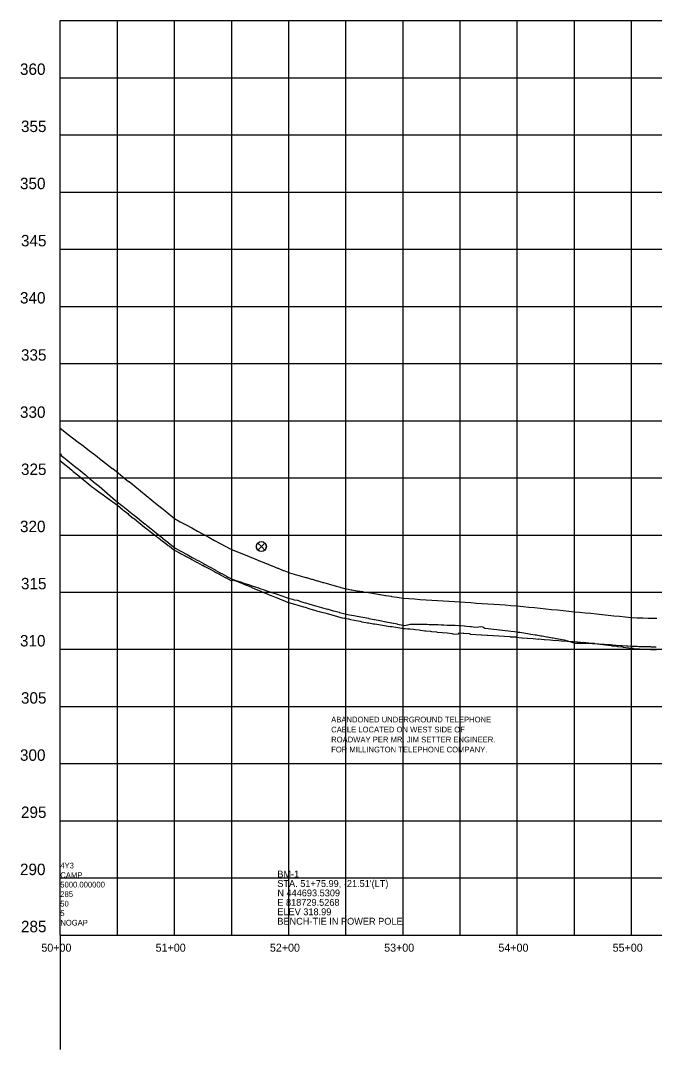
# Model space of a CAD drawing. Extents: x 816928 to 825690, y 436959 to 448212.
# Drawn here: x 817253 to 817808, y 446338 to 447238 of the extents above; entities that cross this region are included whole.
import ezdxf

# ---------------------------------------------------------------- set-up
doc = ezdxf.new("R2010")
doc.units = 0
for name, color, linetype in [('DESIGN - SHEET - Corner Text', 7, 'Continuous'), ('DESIGN - SHEET - Light Grid', 7, 'Continuous'), ('SURVEY - PROFILE - Control with Text', 7, 'Continuous'), ('SURVEY - PROFILE - Ground Line with Text', 7, 'Continuous'), ('SURVEY - PROFILE - Utilities - Gas with Text', 7, 'Continuous'), ('SURVEY - PROFILE - Utilities - Telephone with Text', 7, 'Continuous'), ('SURVEY - PROFILE - Utilities - Water with Text', 7, 'Continuous')]:
    doc.layers.add(name, color=color, linetype=linetype)

msp = doc.modelspace()

# ---------------------------------------------------------------- linework, layer by layer
at = {"layer": 'DESIGN - SHEET - Light Grid'}
for p, q in [((817287.73, 446437.63), (817287.73, 447237.63)), ((817287.73, 446437.63), (817287.73, 447237.63)), ((817287.73, 447237.63), (818716.11, 447237.63)), ((817287.73, 447237.63), (818716.11, 447237.63)), ((817337.73, 446437.63), (817337.73, 447237.63)), ((817387.73, 446437.63), (817387.73, 447237.63)), ((817437.73, 446437.63), (817437.73, 447237.63)), ((817487.73, 446437.63), (817487.73, 447237.63)), ((817537.73, 446437.63), (817537.73, 447237.63)), ((817587.73, 446437.63), (817587.73, 447237.63)), ((817637.73, 446437.63), (817637.73, 447237.63)), ((817687.73, 446437.63), (817687.73, 447237.63)), ((817737.73, 446437.63), (817737.73, 447237.63)), ((817787.73, 446437.63), (817787.73, 447237.63)), ((817287.73, 447187.63), (818716.11, 447187.63)), ((817287.73, 447137.63), (818716.11, 447137.63)), ((817287.73, 447087.63), (818716.11, 447087.63)), ((817287.73, 447037.63), (818716.11, 447037.63)), ((817287.73, 446987.63), (818716.11, 446987.63)), ((817287.73, 446937.63), (818716.11, 446937.63)), ((817287.73, 446887.63), (818716.11, 446887.63)), ((817287.73, 446837.63), (818716.11, 446837.63)), ((817287.73, 446787.63), (818716.11, 446787.63)), ((817287.73, 446737.63), (818716.11, 446737.63)), ((817287.73, 446687.63), (818716.11, 446687.63)), ((817287.73, 446637.63), (818716.11, 446637.63)), ((817287.73, 446587.63), (818716.11, 446587.63)), ((817287.73, 446537.63), (818716.11, 446537.63)), ((817287.73, 446487.63), (818716.11, 446487.63)), ((817287.73, 446437.63), (818716.11, 446437.63)), ((817287.73, 446437.63), (817287.73, 446337.63)), ((817287.73, 446437.63), (818716.11, 446437.63))]:
    msp.add_line(p, q, dxfattribs=at)
at = {"layer": 'SURVEY - PROFILE - Control with Text'}
for p, q in [((817460.64, 446780.58), (817463.72, 446777.5)), ((817463.72, 446777.5), (817466.81, 446780.59)), ((817460.66, 446774.44), (817463.72, 446777.5)), ((817463.72, 446777.5), (817466.8, 446774.43))]:
    msp.add_line(p, q, dxfattribs=at)
for points in [[(817460.66, 446780.57), (817463.72, 446777.5), (817460.67, 446774.45), (817460.42, 446774.7), (817460.16, 446775.03), (817460, 446775.27), (817459.83, 446775.59), (817459.68, 446775.92), (817459.59, 446776.2), (817459.51, 446776.46), (817459.45, 446776.75), (817459.41, 446777.04), (817459.39, 446777.3), (817459.38, 446777.63), (817459.4, 446777.9), (817459.43, 446778.14), (817459.46, 446778.34), (817459.51, 446778.57), (817459.59, 446778.85), (817459.66, 446779.05), (817459.76, 446779.28), (817459.93, 446779.63), (817460.13, 446779.96), (817460.41, 446780.33)], [(817466.8, 446780.57), (817463.72, 446777.5), (817466.79, 446774.43), (817466.98, 446774.63), (817467.21, 446774.91), (817467.44, 446775.24), (817467.58, 446775.49), (817467.77, 446775.9), (817467.87, 446776.18), (817467.95, 446776.47), (817468, 446776.71), (817468.05, 446777.03), (817468.07, 446777.28), (817468.08, 446777.59), (817468.06, 446777.9), (817468.04, 446778.11), (817467.99, 446778.39), (817467.95, 446778.58), (817467.87, 446778.84), (817467.74, 446779.2), (817467.65, 446779.4), (817467.54, 446779.62), (817467.32, 446779.96), (817467.07, 446780.3)]]:
    msp.add_lwpolyline(points, close=True, dxfattribs=at)
msp.add_circle((817463.73, 446777.51), 4.35, dxfattribs=at)
at = {"layer": 'SURVEY - PROFILE - Ground Line with Text'}
msp.add_lwpolyline([(817287.73, 446881.08), (817288.65, 446880.17), (817293.57, 446876.43), (817298.49, 446872.69), (817303.4, 446868.95), (817308.32, 446865.21), (817308.67, 446864.94), (817313.36, 446861.31), (817318.42, 446857.4), (817323.47, 446853.5), (817328.52, 446849.59), (817333.23, 446845.95), (817333.58, 446845.67), (817338.24, 446842.07), (817342.5, 446838.62), (817342.89, 446838.31), (817347.52, 446834.57), (817347.87, 446834.29), (817352.53, 446830.52), (817352.85, 446830.27), (817357.83, 446826.24), (817362.81, 446822.22), (817367.78, 446818.19), (817372.76, 446814.16), (817377.74, 446810.13), (817382.72, 446806.1), (817387.73, 446802.06), (817392.78, 446799.29), (817397.77, 446796.55), (817402.76, 446793.82), (817407.75, 446791.09), (817412.74, 446788.35), (817417.73, 446785.62), (817422.72, 446782.88), (817427.71, 446780.15), (817432.65, 446777.44), (817436.29, 446775.66), (817437.77, 446774.85), (817438.97, 446774.44), (817442.93, 446772.84), (817447.96, 446770.82), (817452.98, 446768.79), (817458, 446766.76), (817462.71, 446764.86), (817463.02, 446764.73), (817467.82, 446762.79), (817468.2, 446762.63), (817472.81, 446760.77), (817473.25, 446760.58), (817477.8, 446758.75), (817478.3, 446758.53), (817482.78, 446756.72), (817483.34, 446756.48), (817487.77, 446754.69), (817488.25, 446754.56), (817492.56, 446753.33), (817493.18, 446753.16), (817497.56, 446751.91), (817498.18, 446751.74), (817502.56, 446750.49), (817503.18, 446750.31), (817507.55, 446749.07), (817508.18, 446748.89), (817512.55, 446747.64), (817513.18, 446747.47), (817517.55, 446746.22), (817518.17, 446746.05), (817522.55, 446744.8), (817523.17, 446744.63), (817527.54, 446743.38), (817528.17, 446743.21), (817532.54, 446741.96), (817533.17, 446741.79), (817537.61, 446740.53), (817538.24, 446740.42), (817542.37, 446739.74), (817542.96, 446739.64), (817547.37, 446738.92), (817547.92, 446738.82), (817552.38, 446738.09), (817552.89, 446738.01), (817557.38, 446737.27), (817557.86, 446737.19), (817562.39, 446736.45), (817562.83, 446736.37), (817567.4, 446735.63), (817567.79, 446735.56), (817572.4, 446734.81), (817572.76, 446734.74), (817577.41, 446733.99), (817577.73, 446733.93), (817582.69, 446733.12), (817587.83, 446732.32), (817592.83, 446731.99), (817597.82, 446731.66), (817602.82, 446731.33), (817607.81, 446731.01), (817612.81, 446730.68), (817617.8, 446730.36), (817622.8, 446730.03), (817627.79, 446729.71), (817632.79, 446729.38), (817637.76, 446729.06), (817642.06, 446728.77), (817647.05, 446728.44), (817652.05, 446728.1), (817657.04, 446727.77), (817662.04, 446727.43), (817667.03, 446727.09), (817672.03, 446726.76), (817677.02, 446726.42), (817682.02, 446726.08), (817686.89, 446725.75), (817687.73, 446725.67), (817692.74, 446725.15), (817697.74, 446724.64), (817702.74, 446724.13), (817707.75, 446723.62), (817712.75, 446723.11), (817717.75, 446722.59), (817722.76, 446722.08), (817727.76, 446721.57), (817732.77, 446721.06), (817737.73, 446720.55), (817742.15, 446720.11), (817747.12, 446719.61), (817752.09, 446719.11), (817757.07, 446718.6), (817759.45, 446718.36), (817762.07, 446718.09), (817767.11, 446717.55), (817772.15, 446717.02), (817777.19, 446716.5), (817782.23, 446715.97), (817787.44, 446715.45), (817792.49, 446715.29), (817797.21, 446715.14), (817797.54, 446715.13), (817802.21, 446714.98), (817802.6, 446714.97), (817804.98, 446714.89), (817807.65, 446714.81), (817809.83, 446714.74)], dxfattribs=at)
at = {"layer": 'SURVEY - PROFILE - Utilities - Gas with Text'}
msp.add_lwpolyline([(817287.83, 446859.06), (817288.39, 446857.74), (817288.6, 446857.24), (817288.63, 446857.21), (817290.74, 446855.57), (817293.63, 446853.19), (817295.53, 446851.71), (817298.64, 446849.15), (817300.29, 446847.85), (817303.64, 446845.09), (817305.04, 446843.99), (817308.65, 446841), (817309.76, 446840.13), (817313.65, 446836.88), (817314.45, 446836.26), (817318.66, 446832.73), (817319.1, 446832.39), (817323.68, 446828.53), (817323.7, 446828.51), (817323.99, 446828.27), (817328.64, 446824.26), (817328.97, 446823.96), (817333.6, 446819.96), (817334.12, 446819.48), (817337.38, 446816.65), (817341.62, 446813.3), (817342.36, 446812.75), (817346.75, 446809.28), (817347.34, 446808.83), (817351.87, 446805.25), (817352.32, 446804.91), (817356.99, 446801.2), (817357.3, 446800.97), (817362.12, 446797.14), (817362.28, 446797.02), (817363.23, 446796.26), (817367.2, 446793.07), (817367.26, 446793.02), (817370.15, 446790.69), (817372.19, 446789.06), (817372.25, 446789.01), (817377.07, 446785.16), (817377.27, 446785), (817381.94, 446781.27), (817382.28, 446781), (817386.82, 446777.38), (817387.29, 446777.01), (817388.32, 446776.19), (817388.77, 446775.94), (817393.25, 446773.49), (817393.8, 446773.19), (817398.24, 446770.76), (817398.82, 446770.44), (817403.22, 446768.03), (817403.85, 446767.69), (817408.21, 446765.3), (817408.87, 446764.93), (817413.2, 446762.57), (817413.9, 446762.18), (817418.19, 446759.84), (817418.92, 446759.43), (817423.17, 446757.1), (817423.95, 446756.67), (817428.16, 446754.37), (817428.97, 446753.92), (817433.15, 446751.64), (817434, 446751.17), (817436.38, 446749.87), (817437.49, 446749.28), (817437.68, 446749.22), (817438.97, 446748.72), (817441.41, 446747.88), (817442.39, 446747.54), (817446.33, 446746.23), (817447.41, 446745.87), (817451.26, 446744.59), (817452.43, 446744.19), (817456.19, 446742.94), (817457.45, 446742.51), (817461.12, 446741.29), (817462.47, 446740.83), (817466.05, 446739.64), (817467.49, 446739.15), (817470.98, 446737.99), (817472.5, 446737.46), (817475.91, 446736.33), (817477.52, 446735.78), (817480.84, 446734.67), (817482.54, 446734.09), (817485.77, 446733.02), (817487.56, 446732.4), (817487.57, 446732.4), (817490.85, 446731.49), (817492.3, 446731.05), (817495.2, 446730.75), (817496.11, 446730.48), (817497.29, 446729.63), (817500.87, 446728.63), (817502.27, 446728.21), (817506.02, 446727.18), (817507.25, 446726.81), (817511.17, 446725.73), (817512.23, 446725.41), (817516.32, 446724.29), (817517.21, 446724.03), (817521.48, 446722.86), (817522.19, 446722.65), (817526.65, 446721.43), (817527.17, 446721.28), (817531.82, 446720.02), (817532.15, 446719.92), (817536.92, 446718.63), (817537, 446718.61), (817537.13, 446718.58), (817537.58, 446718.46), (817537.58, 446718.46), (817542.54, 446717.61), (817542.58, 446717.6), (817544.6, 446717.25), (817547.57, 446716.68), (817547.6, 446716.68), (817552.56, 446715.71), (817552.64, 446715.7), (817557.56, 446714.74), (817557.68, 446714.71), (817562.55, 446713.77), (817562.72, 446713.73), (817567.54, 446712.79), (817567.76, 446712.73), (817572.54, 446711.8), (817572.81, 446711.74), (817577.53, 446710.81), (817577.86, 446710.73), (817582.52, 446709.82), (817582.9, 446709.73), (817587.52, 446708.82), (817587.73, 446708.77), (817589.14, 446708.49), (817594.08, 446709.65), (817594.09, 446709.65), (817594.11, 446709.65), (817598.91, 446709.72), (817599.69, 446709.67), (817603.78, 446709.68), (817605.14, 446709.6), (817608.68, 446709.59), (817610.49, 446709.48), (817613.6, 446709.44), (817615.77, 446709.31), (817618.53, 446709.27), (817621, 446709.12), (817623.48, 446709.07), (817626.19, 446708.9), (817628.44, 446708.85), (817631.35, 446708.67), (817633.4, 446708.62), (817636.49, 446708.43), (817638.36, 446708.37), (817641.31, 446708.06), (817641.56, 446708.03), (817643.29, 446707.96), (817646.6, 446707.59), (817647.49, 446707.55), (817649.21, 446707.34), (817652.45, 446706.98), (817655.14, 446707.53), (817657.49, 446707.28), (817659.42, 446706.16), (817662.35, 446705.84), (817664.54, 446705.57), (817667.29, 446705.26), (817669.67, 446704.96), (817672.23, 446704.67), (817674.82, 446704.35), (817677.16, 446704.09), (817679.98, 446703.73), (817682.08, 446703.5), (817685.17, 446703.1), (817686.98, 446702.9), (817688.43, 446702.71), (817689.96, 446702.52), (817693.33, 446701.94), (817694.83, 446701.75), (817698.37, 446701.13), (817699.7, 446700.96), (817703.4, 446700.3), (817704.57, 446700.16), (817708.44, 446699.46), (817709.42, 446699.34), (817713.48, 446698.59), (817714.25, 446698.49), (817718.53, 446697.7), (817719.08, 446697.63), (817723.58, 446696.78), (817723.89, 446696.74), (817728.63, 446695.82), (817728.69, 446695.82), (817729.75, 446695.61), (817733.62, 446694.35), (817733.69, 446694.33), (817737.05, 446693.24), (817738.6, 446692.96), (817738.66, 446692.95), (817743.58, 446693.04), (817743.65, 446693.04), (817748.63, 446693.14), (817748.63, 446693.14), (817748.79, 446693.14), (817753.57, 446692.8), (817753.77, 446692.79), (817758.51, 446692.45), (817758.91, 446692.42), (817763.45, 446692.1), (817764.04, 446692.06), (817768.39, 446691.75), (817769.17, 446691.7), (817773.33, 446691.4), (817774.29, 446691.34), (817778.28, 446691.06), (817779.41, 446690.98), (817783.22, 446690.71), (817784.52, 446690.62), (817787.62, 446690.4), (817787.68, 446690.4), (817789.09, 446690.36), (817792.67, 446690.28), (817794.18, 446690.23), (817797.66, 446690.15), (817799.27, 446690.1), (817802.65, 446690.02), (817804.35, 446689.97), (817804.98, 446689.95), (817807.6, 446689.89), (817809.36, 446689.83)], dxfattribs=at)
at = {"layer": 'SURVEY - PROFILE - Utilities - Water with Text'}
msp.add_lwpolyline([(817287.73, 446852.61), (817287.73, 446852.61), (817287.87, 446852.5), (817288.89, 446851.63), (817292.82, 446848.47), (817293.99, 446847.47), (817297.76, 446844.43), (817299.08, 446843.3), (817302.71, 446840.37), (817304.17, 446839.13), (817307.66, 446836.31), (817309.25, 446834.95), (817312.61, 446832.22), (817314.32, 446830.77), (817315.08, 446830.15), (817317.61, 446828.33), (817319.17, 446827.14), (817322.65, 446824.63), (817323.99, 446823.62), (817327.69, 446820.95), (817328.82, 446820.11), (817332.73, 446817.29), (817333.65, 446816.6), (817337.77, 446813.65), (817337.97, 446813.5), (817341.79, 446810.35), (817342.57, 446809.76), (817346.7, 446806.36), (817347.56, 446805.71), (817351.6, 446802.38), (817352.56, 446801.67), (817356.49, 446798.43), (817357.55, 446797.64), (817361.36, 446794.51), (817362.55, 446793.64), (817363.45, 446792.89), (817366.28, 446790.63), (817367.54, 446789.74), (817371.24, 446786.77), (817372.52, 446785.88), (817373.73, 446785.04), (817377.21, 446782.22), (817378.58, 446781.44), (817382.22, 446778.48), (817383.43, 446777.77), (817387.22, 446774.66), (817388.29, 446774.03), (817392.04, 446772.05), (817393.03, 446771.46), (817397.04, 446769.35), (817397.96, 446768.81), (817402.04, 446766.66), (817402.89, 446766.16), (817407.03, 446763.98), (817407.82, 446763.52), (817412.03, 446761.31), (817412.76, 446760.88), (817414.14, 446760.16), (817417.02, 446758.63), (817417.76, 446758.2), (817422.01, 446755.94), (817422.79, 446755.49), (817427, 446753.25), (817427.82, 446752.78), (817431.99, 446750.56), (817432.85, 446750.06), (817436.98, 446747.86), (817437.15, 446747.76), (817438.65, 446747.99), (817438.97, 446748.15), (817439.59, 446748.31), (817440.5, 446747.93), (817444.93, 446746.08), (817445.2, 446745.97), (817449.93, 446743.99), (817450.07, 446743.95), (817454.96, 446741.91), (817455.31, 446741.85), (817460.15, 446739.81), (817460.23, 446739.77), (817463.25, 446738.5), (817465.04, 446737.77), (817465.07, 446737.66), (817466.98, 446736.86), (817467.28, 446736.75), (817471.88, 446734.83), (817472.35, 446734.67), (817476.77, 446732.82), (817477.42, 446732.61), (817481.65, 446730.85), (817482.49, 446730.58), (817486.52, 446728.92), (817487.58, 446728.58), (817490.57, 446727.75), (817491.77, 446727.37), (817495.53, 446726.32), (817496.85, 446725.89), (817500.47, 446724.89), (817501.96, 446724.39), (817505.4, 446723.44), (817507.11, 446722.85), (817510.3, 446721.97), (817511.33, 446721.6), (817511.95, 446721.43), (817514.28, 446720.78), (817516.31, 446720.25), (817519.35, 446719.41), (817521.3, 446718.9), (817524.41, 446718.04), (817526.28, 446717.55), (817529.45, 446716.67), (817531.27, 446716.19), (817534.49, 446715.3), (817536.26, 446714.83), (817536.63, 446714.77), (817539.95, 446714.19), (817541.63, 446713.76), (817545.05, 446713.16), (817546.62, 446712.76), (817550.14, 446712.15), (817551.61, 446711.78), (817555.22, 446711.16), (817556.52, 446710.84), (817557.91, 446710.66), (817561.51, 446710.04), (817562.95, 446709.86), (817566.51, 446709.24), (817568, 446709.06), (817571.51, 446708.45), (817573.05, 446708.27), (817576.51, 446707.67), (817578.11, 446707.48), (817581.51, 446706.89), (817583.17, 446706.7), (817586.51, 446706.12), (817586.8, 446706.09), (817588.54, 446705.9), (817589.44, 446705.82), (817591.79, 446705.61), (817593.63, 446705.41), (817596.78, 446705.13), (817598.74, 446704.91), (817601.77, 446704.64), (817601.77, 446704.64), (817603.06, 446704.27), (817606.83, 446703.94), (817607.75, 446703.74), (817611.85, 446703.38), (817612.57, 446703.25), (817616.87, 446702.87), (817617.45, 446702.78), (817621.88, 446702.39), (817621.94, 446702.38), (817626.39, 446701.99), (817630.84, 446701.6), (817631.3, 446701.2), (817636.02, 446700.79), (817636.63, 446701.95), (817640.46, 446701.75), (817640.87, 446701.73), (817645.79, 446701.45), (817646.48, 446700.81), (817646.54, 446700.78), (817651.47, 446700.53), (817651.53, 446700.49), (817656.46, 446700.25), (817656.53, 446700.2), (817661.45, 446699.96), (817661.52, 446699.91), (817666.44, 446699.67), (817666.51, 446699.61), (817671.43, 446699.38), (817671.51, 446699.31), (817676.42, 446699.08), (817676.5, 446698.99), (817681.41, 446698.76), (817681.5, 446698.65), (817686.4, 446698.44), (817686.58, 446698.42), (817686.69, 446698.26), (817691.6, 446697.77), (817691.83, 446697.75), (817696.47, 446697.33), (817696.61, 446697.44), (817696.67, 446697.49), (817701.48, 446697.07), (817706.27, 446696.65), (817706.48, 446696.67), (817711.26, 446696.26), (817711.48, 446696.28), (817716.25, 446695.87), (817716.48, 446695.9), (817721.24, 446695.49), (817721.48, 446695.51), (817726.23, 446695.11), (817726.48, 446695.14), (817731.22, 446694.73), (817731.48, 446694.76), (817736.21, 446694.36), (817736.48, 446694.39), (817740.08, 446694.1), (817740.35, 446694.13), (817743.42, 446693.88), (817745.08, 446693.72), (817745.35, 446693.75), (817750.06, 446693.29), (817750.33, 446693.31), (817755.01, 446692.87), (817755.34, 446692.72), (817759.99, 446692.26), (817760.34, 446692.1), (817764.97, 446691.63), (817765.34, 446691.47), (817769.96, 446690.99), (817770.35, 446690.82), (817774.94, 446690.34), (817775.35, 446690.16), (817779.92, 446689.67), (817780.35, 446689.48), (817784.9, 446688.99), (817785.36, 446688.79), (817789.11, 446688.5), (817789.34, 446688.4), (817789.78, 446688.44), (817793.76, 446688.13), (817794.34, 446688.08), (817794.77, 446688.12), (817799.34, 446687.74), (817799.76, 446687.78), (817804.34, 446687.4), (817804.76, 446687.44), (817804.98, 446687.44), (817809.39, 446687.06)], dxfattribs=at)

# ---------------------------------------------------------------- texts
at = {"layer": 'DESIGN - SHEET - Corner Text'}
for s, height, p in [('360', 10, (817252.45, 447190.13)), ('355', 10, (817253.31, 447140.13)), ('350', 10, (817252.45, 447090.13)), ('345', 10, (817253.31, 447040.13)), ('340', 10, (817252.45, 446990.13)), ('335', 10, (817253.31, 446940.13)), ('330', 10, (817252.45, 446890.13)), ('325', 10, (817253.31, 446840.13)), ('320', 10, (817252.45, 446790.13)), ('315', 10, (817253.31, 446740.13)), ('310', 10, (817252.45, 446690.13)), ('305', 10, (817253.31, 446640.13)), ('300', 10, (817252.45, 446590.13)), ('295', 10, (817253.31, 446540.13)), ('290', 10, (817252.45, 446490.13)), ('285', 10, (817253.31, 446440.13)), ('50+00', 7, (817271.18, 446423.13)), ('51+00', 7, (817371.18, 446423.13)), ('52+00', 7, (817471.18, 446423.13)), ('53+00', 7, (817571.18, 446423.13)), ('54+00', 7, (817671.18, 446423.13)), ('55+00', 7, (817771.18, 446423.13))]:
    msp.add_text(s, height=height, dxfattribs=at).set_placement(p)
at = {"layer": 'DESIGN - SHEET - Light Grid'}
for s, p in [('4Y3', (817287.73, 446495.97)), ('CAMP', (817287.73, 446487.63)), ('5000.000000', (817287.73, 446479.3)), ('285', (817287.73, 446470.97)), ('50', (817287.73, 446462.63)), ('5', (817287.73, 446454.3)), ('NOGAP', (817287.73, 446445.97))]:
    msp.add_text(s, height=5, dxfattribs=at).set_placement(p)
at = {"layer": 'SURVEY - PROFILE - Control with Text'}
for s, p in [('BM-1', (817477.68, 446488.01)), ("STA. 51+75.99, -21.51'(LT)", (817477.68, 446479.76)), ('N 444693.5309', (817477.68, 446471.51)), ('E 818729.5268', (817477.68, 446463.26)), ('ELEV 318.99', (817477.68, 446455.01)), ('BENCH-TIE IN POWER POLE', (817477.68, 446446.76))]:
    msp.add_text(s, height=6, dxfattribs=at).set_placement(p)
at = {"layer": 'SURVEY - PROFILE - Utilities - Telephone with Text'}
for s, p in [('ABANDONED UNDERGROUND TELEPHONE', (817524.8, 446623.69)), ('CABLE LOCATED ON WEST SIDE OF', (817524.8, 446614.94)), ('ROADWAY PER MR. JIM SETTER ENGINEER. ', (817524.8, 446606.19)), ('FOR MILLINGTON TELEPHONE COMPANY.', (817524.8, 446597.44))]:
    msp.add_text(s, height=5, dxfattribs=at).set_placement(p)

doc.saveas('drawing.dxf')
